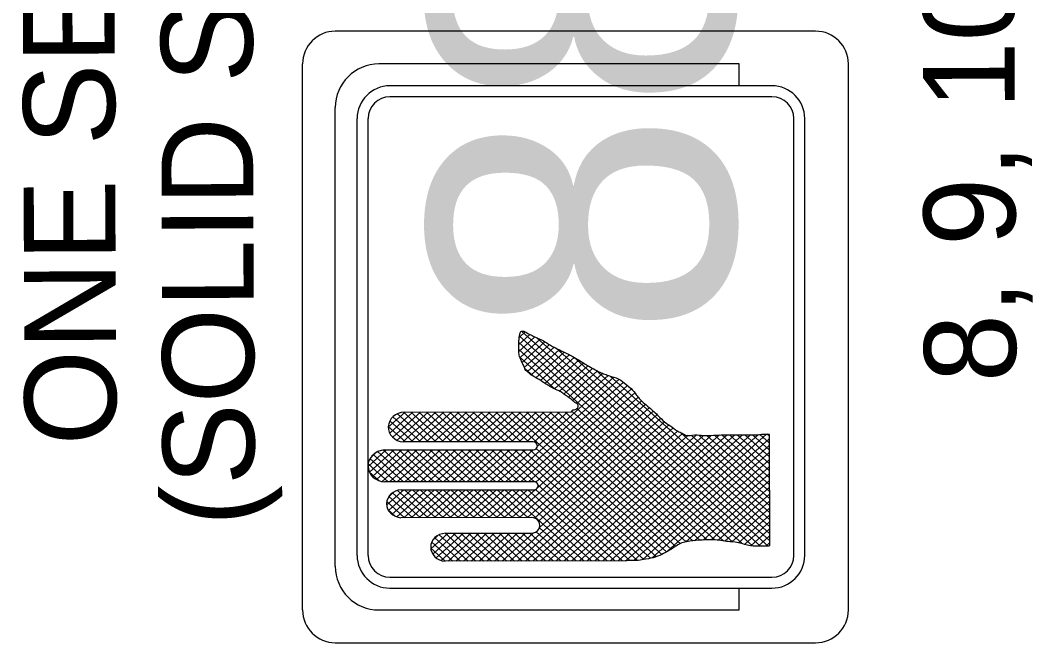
# Model space of a CAD drawing. Extents: x 610543 to 611161, y 419122 to 420064.
# Drawn here: x 610569.3 to 610615.67, y 419375.36 to 419403.86 of the extents above; entities that cross this region are included whole.
import ezdxf

# ---------------------------------------------------------------- set-up
doc = ezdxf.new("R2010")
doc.units = 0
doc.layers.add('C-ANNO-TEXT', color=7, linetype='Continuous')
doc.layers.add('T_Drafting', color=7, linetype='Continuous')

msp = doc.modelspace()

# ---------------------------------------------------------------- linework, layer by layer
at = {"layer": 'T_Drafting'}
for p, q in [((610605.728, 419403.359), (610583.728, 419403.359)), ((610582.228, 419376.859), (610582.228, 419401.859)), ((610602.228, 419401.859), (610585.728, 419401.859)), ((610602.228, 419400.859), (610602.228, 419401.859)), ((610607.228, 419376.859), (610607.228, 419401.859)), ((610603.728, 419400.859), (610586.228, 419400.859)), ((610603.728, 419400.359), (610586.228, 419400.359)), ((610583.728, 419378.859), (610583.728, 419399.859)), ((610584.728, 419379.359), (610584.728, 419399.359)), ((610585.228, 419379.359), (610585.228, 419399.359)), ((610604.728, 419379.359), (610604.728, 419399.359)), ((610605.228, 419379.359), (610605.228, 419399.359)), ((610592.13, 419389.01), (610592.643, 419389.472)), ((610592.131, 419388.693), (610592.871, 419389.359)), ((610592.157, 419389.352), (610592.413, 419389.583)), ((610602.836, 419379.792), (610592.163, 419389.397)), ((610603.201, 419379.782), (610592.26, 419389.628)), ((610602.366, 419379.897), (610592.131, 419389.108)), ((610592.188, 419388.426), (610593.112, 419389.257)), ((610592.28, 419388.19), (610593.33, 419389.135)), ((610592.384, 419387.966), (610593.541, 419389.007)), ((610592.519, 419387.769), (610593.759, 419388.885)), ((610603.554, 419379.782), (610592.955, 419389.321)), ((610601.934, 419379.968), (610592.131, 419388.79)), ((610593.809, 419386.961), (610592.192, 419388.417)), ((610592.705, 419387.618), (610593.988, 419388.773)), ((610592.912, 419387.487), (610594.217, 419388.661)), ((610593.131, 419387.366), (610594.44, 419388.543)), ((610593.33, 419387.226), (610594.661, 419388.424)), ((610603.613, 419380.047), (610593.837, 419388.846)), ((610603.613, 419380.366), (610594.655, 419388.427)), ((610593.546, 419387.102), (610594.879, 419388.302)), ((610593.766, 419386.982), (610595.089, 419388.173)), ((610594.002, 419386.876), (610595.296, 419388.042)), ((610592.787, 419387.563), (610592.407, 419387.905)), ((610592.982, 419384.367), (610596.482, 419387.517)), ((610594.201, 419386.738), (610595.515, 419387.92)), ((610594.406, 419386.604), (610595.737, 419387.801)), ((610594.595, 419386.456), (610595.97, 419387.693)), ((610594.783, 419386.307), (610596.219, 419387.599)), ((610603.612, 419380.684), (610595.656, 419387.845)), ((610603.612, 419381.003), (610596.324, 419387.562)), ((610591.516, 419382.73), (610596.731, 419387.424)), ((610591.87, 419382.73), (610596.93, 419387.284)), ((610592.224, 419382.73), (610597.116, 419387.134)), ((610592.578, 419382.731), (610597.296, 419386.977)), ((610592.908, 419382.71), (610597.449, 419386.797)), ((610592.998, 419382.473), (610597.594, 419386.609)), ((610591.816, 419381.091), (610597.757, 419386.437)), ((610592.17, 419381.091), (610597.936, 419386.28)), ((610592.524, 419381.092), (610598.116, 419386.124)), ((610601.53, 419380.013), (610594.783, 419386.085)), ((610586.154, 419385.223), (610586.923, 419385.915)), ((610586.217, 419384.961), (610587.277, 419385.915)), ((610586.357, 419384.769), (610587.631, 419385.916)), ((610587.645, 419384.555), (610586.366, 419385.706)), ((610586.557, 419384.63), (610587.985, 419385.916)), ((610587.998, 419384.555), (610586.569, 419385.841)), ((610586.827, 419384.555), (610588.339, 419385.916)), ((610588.351, 419384.555), (610586.843, 419385.912)), ((610586.892, 419385.915), (610594.549, 419385.924)), ((610587.179, 419384.554), (610588.693, 419385.917)), ((610588.704, 419384.556), (610587.194, 419385.915)), ((610587.533, 419384.554), (610589.047, 419385.917)), ((610589.057, 419384.556), (610587.547, 419385.915)), ((610587.887, 419384.555), (610589.401, 419385.917)), ((610589.41, 419384.557), (610587.9, 419385.916)), ((610588.241, 419384.555), (610589.755, 419385.918)), ((610589.763, 419384.557), (610588.253, 419385.916)), ((610588.595, 419384.556), (610590.109, 419385.918)), ((610590.116, 419384.557), (610588.606, 419385.917)), ((610588.949, 419384.556), (610590.463, 419385.918)), ((610590.47, 419384.558), (610588.959, 419385.917)), ((610589.303, 419384.556), (610590.817, 419385.919)), ((610590.823, 419384.558), (610589.313, 419385.917)), ((610589.657, 419384.557), (610591.171, 419385.919)), ((610591.176, 419384.559), (610589.666, 419385.918)), ((610590.011, 419384.557), (610591.524, 419385.92)), ((610591.529, 419384.559), (610590.019, 419385.918)), ((610590.365, 419384.558), (610591.878, 419385.92)), ((610591.882, 419384.559), (610590.372, 419385.918)), ((610590.719, 419384.558), (610592.232, 419385.92)), ((610592.235, 419384.56), (610590.725, 419385.919)), ((610591.073, 419384.558), (610592.586, 419385.921)), ((610592.588, 419384.56), (610591.078, 419385.919)), ((610591.427, 419384.559), (610592.94, 419385.921)), ((610598.676, 419379.399), (610591.432, 419385.919)), ((610591.781, 419384.559), (610593.294, 419385.921)), ((610598.893, 419379.522), (610591.785, 419385.92)), ((610592.135, 419384.56), (610593.648, 419385.922)), ((610599.108, 419379.647), (610592.138, 419385.92)), ((610592.489, 419384.56), (610594.002, 419385.922)), ((610599.323, 419379.771), (610592.491, 419385.921)), ((610592.835, 419384.553), (610594.356, 419385.922)), ((610599.542, 419379.892), (610592.844, 419385.921)), ((610592.849, 419381.066), (610598.29, 419385.962)), ((610593.041, 419380.92), (610598.462, 419385.8)), ((610593.086, 419380.643), (610598.636, 419385.637)), ((610599.791, 419379.987), (610593.197, 419385.921)), ((610600.105, 419380.022), (610593.55, 419385.922)), ((610600.425, 419380.052), (610593.904, 419385.922)), ((610600.758, 419380.071), (610594.257, 419385.922)), ((610601.114, 419380.069), (610594.559, 419385.968)), ((610586.938, 419384.554), (610586.154, 419385.259)), ((610587.292, 419384.554), (610586.222, 419385.516)), ((610591.726, 419379.1), (610598.812, 419385.478)), ((610592.08, 419379.101), (610599.001, 419385.33)), ((610592.434, 419379.101), (610599.206, 419385.196)), ((610592.788, 419379.102), (610599.4, 419385.053)), ((610593.142, 419379.102), (610599.629, 419384.941)), ((610593.496, 419379.102), (610599.89, 419384.857)), ((610593.85, 419379.103), (610600.256, 419384.868)), ((610594.204, 419379.103), (610600.593, 419384.854)), ((610594.558, 419379.103), (610600.948, 419384.855)), ((610594.912, 419379.104), (610601.319, 419384.871)), ((610595.266, 419379.104), (610601.675, 419384.872)), ((610595.62, 419379.105), (610602.029, 419384.873)), ((610595.974, 419379.105), (610602.383, 419384.873)), ((610596.328, 419379.105), (610602.739, 419384.875)), ((610596.682, 419379.106), (610603.108, 419384.889)), ((610597.038, 419379.108), (610603.484, 419384.909)), ((610597.405, 419379.121), (610603.606, 419384.702)), ((610603.611, 419381.322), (610599.53, 419384.995)), ((610603.611, 419381.64), (610600.029, 419384.864)), ((610603.61, 419381.959), (610600.385, 419384.862)), ((610603.61, 419382.277), (610600.749, 419384.852)), ((610603.609, 419382.596), (610601.094, 419384.86)), ((610603.609, 419382.915), (610601.434, 419384.872)), ((610603.609, 419383.233), (610601.787, 419384.872)), ((610603.608, 419383.552), (610602.14, 419384.873)), ((610603.608, 419383.87), (610602.493, 419384.873)), ((610603.607, 419384.189), (610602.841, 419384.878)), ((610603.607, 419384.508), (610603.179, 419384.893)), ((610603.606, 419384.826), (610603.514, 419384.909)), ((610603.612, 419384.91), (610603.606, 419384.887)), ((610603.606, 419384.887), (610603.613, 419379.807)), ((610592.793, 419384.561), (610586.845, 419384.554)), ((610598.442, 419379.291), (610592.93, 419384.252)), ((610597.814, 419379.17), (610603.607, 419384.384)), ((610585.225, 419383.432), (610586.064, 419384.187)), ((610585.288, 419383.171), (610586.418, 419384.187)), ((610586.497, 419382.724), (610585.313, 419383.789)), ((610585.389, 419383.898), (610585.547, 419384.04)), ((610585.424, 419382.975), (610586.772, 419384.188)), ((610586.85, 419382.724), (610585.462, 419383.973)), ((610585.616, 419382.829), (610587.126, 419384.188)), ((610587.203, 419382.725), (610585.666, 419384.108)), ((610585.869, 419382.739), (610587.48, 419384.189)), ((610587.556, 419382.725), (610585.936, 419384.183)), ((610585.982, 419384.187), (610592.76, 419384.194)), ((610586.206, 419382.724), (610587.834, 419384.189)), ((610587.909, 419382.726), (610586.285, 419384.187)), ((610586.56, 419382.724), (610588.188, 419384.189)), ((610588.262, 419382.726), (610586.638, 419384.188)), ((610586.914, 419382.724), (610588.542, 419384.19)), ((610588.615, 419382.726), (610586.991, 419384.188)), ((610587.268, 419382.725), (610588.896, 419384.19)), ((610588.968, 419382.727), (610587.344, 419384.188)), ((610587.622, 419382.725), (610589.25, 419384.19)), ((610589.322, 419382.727), (610587.698, 419384.189)), ((610587.976, 419382.726), (610589.604, 419384.191)), ((610589.675, 419382.728), (610588.051, 419384.189)), ((610588.33, 419382.726), (610589.958, 419384.191)), ((610590.028, 419382.728), (610588.404, 419384.19)), ((610588.684, 419382.726), (610590.312, 419384.192)), ((610590.381, 419382.728), (610588.757, 419384.19)), ((610589.038, 419382.727), (610590.666, 419384.192)), ((610590.734, 419382.729), (610589.11, 419384.19)), ((610589.392, 419382.727), (610591.02, 419384.192)), ((610591.087, 419382.729), (610589.463, 419384.191)), ((610589.746, 419382.728), (610591.374, 419384.193)), ((610591.44, 419382.73), (610589.816, 419384.191)), ((610590.1, 419382.728), (610591.728, 419384.193)), ((610591.793, 419382.73), (610590.169, 419384.192)), ((610590.454, 419382.728), (610592.082, 419384.194)), ((610592.146, 419382.73), (610590.523, 419384.192)), ((610590.808, 419382.729), (610592.436, 419384.194)), ((610592.5, 419382.731), (610590.876, 419384.192)), ((610591.162, 419382.729), (610592.783, 419384.189)), ((610592.857, 419382.727), (610591.229, 419384.193)), ((610597.221, 419379.118), (610591.582, 419384.193)), ((610597.562, 419379.129), (610591.935, 419384.193)), ((610597.861, 419379.178), (610592.288, 419384.194)), ((610598.16, 419379.227), (610592.641, 419384.194)), ((610598.247, 419379.242), (610603.607, 419384.066)), ((610586.144, 419382.724), (610585.23, 419383.545)), ((610598.947, 419379.554), (610603.608, 419383.748)), ((610599.779, 419379.984), (610603.608, 419383.431)), ((610585.731, 419382.777), (610585.285, 419383.178)), ((610600.184, 419380.03), (610603.609, 419383.113)), ((610592.828, 419382.731), (610586.001, 419382.723)), ((610591.462, 419381.091), (610592.896, 419382.381)), ((610596.528, 419379.106), (610592.891, 419382.379)), ((610596.881, 419379.106), (610593.011, 419382.589)), ((610600.573, 419380.062), (610603.609, 419382.795)), ((610600.94, 419380.074), (610603.61, 419382.477)), ((610586.079, 419381.655), (610586.861, 419382.359)), ((610586.163, 419381.413), (610587.215, 419382.359)), ((610587.256, 419381.086), (610586.18, 419382.055)), ((610586.197, 419382.08), (610586.385, 419382.249)), ((610586.322, 419381.237), (610587.569, 419382.359)), ((610587.609, 419381.086), (610586.346, 419382.223)), ((610586.546, 419381.121), (610587.923, 419382.36)), ((610587.963, 419381.087), (610586.579, 419382.332)), ((610586.75, 419382.358), (610592.796, 419382.365)), ((610586.86, 419381.085), (610588.277, 419382.36)), ((610588.316, 419381.087), (610586.903, 419382.359)), ((610587.214, 419381.086), (610588.631, 419382.361)), ((610588.669, 419381.087), (610587.256, 419382.359)), ((610587.568, 419381.086), (610588.985, 419382.361)), ((610589.022, 419381.088), (610587.609, 419382.359)), ((610587.922, 419381.087), (610589.339, 419382.361)), ((610589.375, 419381.088), (610587.962, 419382.36)), ((610588.276, 419381.087), (610589.693, 419382.362)), ((610589.728, 419381.089), (610588.315, 419382.36)), ((610588.63, 419381.087), (610590.047, 419382.362)), ((610590.081, 419381.089), (610588.668, 419382.361)), ((610588.984, 419381.088), (610590.401, 419382.363)), ((610590.434, 419381.089), (610589.021, 419382.361)), ((610589.338, 419381.088), (610590.755, 419382.363)), ((610590.787, 419381.09), (610589.374, 419382.361)), ((610589.692, 419381.089), (610591.109, 419382.363)), ((610591.14, 419381.09), (610589.728, 419382.362)), ((610590.046, 419381.089), (610591.463, 419382.364)), ((610591.494, 419381.091), (610590.081, 419382.362)), ((610590.4, 419381.089), (610591.817, 419382.364)), ((610591.847, 419381.091), (610590.434, 419382.363)), ((610590.754, 419381.09), (610592.171, 419382.365)), ((610592.2, 419381.091), (610590.787, 419382.363)), ((610591.108, 419381.09), (610592.525, 419382.365)), ((610592.553, 419381.092), (610591.14, 419382.363)), ((610595.115, 419379.104), (610591.493, 419382.364)), ((610595.468, 419379.104), (610591.846, 419382.364)), ((610595.821, 419379.105), (610592.199, 419382.365)), ((610596.174, 419379.105), (610592.552, 419382.365)), ((610601.27, 419380.054), (610603.61, 419382.159)), ((610586.903, 419381.085), (610586.084, 419381.823)), ((610586.486, 419381.143), (610586.14, 419381.454)), ((610601.572, 419380.007), (610603.61, 419381.842)), ((610601.887, 419379.972), (610603.611, 419381.524)), ((610592.701, 419381.092), (610586.736, 419381.085)), ((610602.201, 419379.937), (610603.611, 419381.206)), ((610594.762, 419379.104), (610593.078, 419380.619)), ((610602.472, 419379.862), (610603.612, 419380.888)), ((610602.753, 419379.797), (610603.612, 419380.57)), ((610588.101, 419379.656), (610588.894, 419380.371)), ((610588.189, 419379.417), (610589.248, 419380.371)), ((610588.195, 419380.059), (610588.442, 419380.282)), ((610589.465, 419379.098), (610588.281, 419380.164)), ((610588.35, 419379.244), (610589.602, 419380.371)), ((610589.818, 419379.098), (610588.482, 419380.301)), ((610588.576, 419379.13), (610589.956, 419380.372)), ((610590.171, 419379.099), (610588.759, 419380.37)), ((610588.771, 419380.37), (610592.702, 419380.375)), ((610588.894, 419379.097), (610590.31, 419380.372)), ((610590.524, 419379.099), (610589.111, 419380.371)), ((610589.248, 419379.098), (610590.664, 419380.373)), ((610590.878, 419379.099), (610589.465, 419380.371)), ((610589.602, 419379.098), (610591.018, 419380.373)), ((610591.231, 419379.1), (610589.818, 419380.372)), ((610589.956, 419379.098), (610591.372, 419380.373)), ((610591.584, 419379.1), (610590.171, 419380.372)), ((610590.31, 419379.099), (610591.726, 419380.374)), ((610591.937, 419379.101), (610590.524, 419380.372)), ((610590.664, 419379.099), (610592.08, 419380.374)), ((610592.29, 419379.101), (610590.877, 419380.373)), ((610591.018, 419379.1), (610592.434, 419380.375)), ((610592.643, 419379.101), (610591.23, 419380.373)), ((610591.372, 419379.1), (610592.801, 419380.386)), ((610592.996, 419379.102), (610591.583, 419380.374)), ((610593.349, 419379.102), (610591.936, 419380.374)), ((610593.703, 419379.103), (610592.289, 419380.374)), ((610594.056, 419379.103), (610592.642, 419380.375)), ((610594.409, 419379.103), (610592.926, 419380.438)), ((610603.091, 419379.783), (610603.613, 419380.253)), ((610588.759, 419379.097), (610588.097, 419379.693)), ((610589.112, 419379.098), (610588.145, 419379.968)), ((610603.443, 419379.782), (610603.613, 419379.935)), ((610603.613, 419379.807), (610603.581, 419379.782)), ((610596.999, 419379.106), (610588.756, 419379.097)), ((610586.228, 419378.359), (610603.728, 419378.359)), ((610586.228, 419377.859), (610603.728, 419377.859)), ((610602.228, 419376.859), (610602.228, 419377.859)), ((610585.728, 419376.859), (610602.228, 419376.859)), ((610583.728, 419375.359), (610605.728, 419375.359))]:
    msp.add_line(p, q, dxfattribs=at)
for centre, radius, start, end in [((610583.728, 419401.859), 1.5, 90, 180), ((610605.728, 419401.859), 1.5, 0, 90), ((610585.728, 419399.859), 2, 90, 180), ((610586.228, 419399.359), 1.5, 90, 180), ((610603.728, 419399.359), 1.5, 0, 90), ((610586.228, 419399.359), 1, 90, 180), ((610603.728, 419399.359), 1, 0, 90), ((610586.228, 419379.359), 1.5, 180, 270), ((610586.228, 419379.359), 1, 180, 270), ((610603.728, 419379.359), 1.5, 270, 360), ((610603.728, 419379.359), 1, 270, 360), ((610585.728, 419378.859), 2, 180, 270), ((610583.728, 419376.859), 1.5, 180, 270), ((610605.728, 419376.859), 1.5, 270, 360)]:
    msp.add_arc(centre, radius, start, end, dxfattribs=at)
for centre, major_axis, start_param, end_param in [((610586.912, 419385.233), (0.758, 0), 1.597842, 4.623315), ((610592.775, 419384.375), (0.207, 0), 4.624552, 7.766145), ((610586.039, 419383.456), (0.814, 0), 1.640121, 4.665593), ((610592.812, 419382.548), (0.204, 0), 4.633755, 7.775348), ((610586.784, 419381.721), (0.709, 0), 1.618611, 4.644084), ((610592.701, 419380.733), (0.398, 0), 4.713646, 7.855239), ((610588.804, 419379.733), (0.709, 0), 1.618611, 4.644084)]:
    msp.add_ellipse(centre, major_axis=major_axis, ratio=0.9, start_param=start_param, end_param=end_param, dxfattribs=at)
for points in [[(610594.548, 419385.923), (610594.562, 419385.974), (610594.717, 419386.043), (610594.835, 419386.132), (610594.854, 419386.184), (610594.835, 419386.271), (610594.755, 419386.325), (610594.561, 419386.483), (610594.403, 419386.606), (610594.287, 419386.677), (610594.189, 419386.747), (610594.012, 419386.87), (610593.855, 419386.94), (610593.641, 419387.045), (610593.523, 419387.116), (610593.309, 419387.239), (610593.112, 419387.378), (610592.917, 419387.484), (610592.721, 419387.606), (610592.584, 419387.713), (610592.427, 419387.87), (610592.348, 419388.063), (610592.289, 419388.169), (610592.231, 419388.327), (610592.171, 419388.468), (610592.131, 419388.68), (610592.131, 419388.856), (610592.13, 419389.084), (610592.15, 419389.296), (610592.189, 419389.542), (610592.23, 419389.612), (610592.287, 419389.628), (610592.541, 419389.525), (610592.679, 419389.454), (610592.817, 419389.385), (610592.972, 419389.314), (610593.07, 419389.278), (610593.325, 419389.138), (610593.677, 419388.929), (610594.244, 419388.647), (610594.891, 419388.295), (610595.342, 419388.015), (610595.635, 419387.856), (610595.91, 419387.717), (610596.127, 419387.634), (610596.238, 419387.591), (610596.711, 419387.434), (610597.044, 419387.19), (610597.278, 419386.996), (610597.515, 419386.715), (610597.652, 419386.539), (610598.162, 419386.082), (610598.591, 419385.679), (610598.885, 419385.415), (610599.22, 419385.186), (610599.365, 419385.072), (610599.57, 419384.976), (610599.767, 419384.87), (610600.197, 419384.871), (610600.583, 419384.854), (610600.937, 419384.854), (610601.405, 419384.872), (610601.855, 419384.872), (610602.579, 419384.873), (610603.162, 419384.892), (610603.378, 419384.909), (610603.536, 419384.909), (610603.611, 419384.91)], [(610603.581, 419379.782), (610603.267, 419379.782), (610602.74, 419379.798), (610602.192, 419379.938), (610601.566, 419380.008), (610601.214, 419380.06), (610600.529, 419380.06), (610599.962, 419380.006), (610599.669, 419379.952), (610599.18, 419379.689), (610598.691, 419379.407), (610598.28, 419379.248), (610597.85, 419379.176), (610597.517, 419379.123), (610597.303, 419379.123), (610596.999, 419379.106)]]:
    msp.add_spline(points, degree=3, dxfattribs=at)

# ---------------------------------------------------------------- texts
at = {"layer": 'C-ANNO-TEXT'}
for s, p in [('(SOLID SYMBOL)', (610580.036, 419380.71)), ('ONE SECTION ', (610573.7, 419384.403)), ('8, 9, 10, & 11', (610614.908, 419387.289))]:
    msp.add_text(s, height=4.2, rotation=90.2455, dxfattribs=at).set_placement(p)
at = {"layer": 'T_Drafting'}
msp.add_text('88', height=14, rotation=90.072, dxfattribs=at).set_placement((610602.007, 419389.324))

doc.saveas('drawing.dxf')
